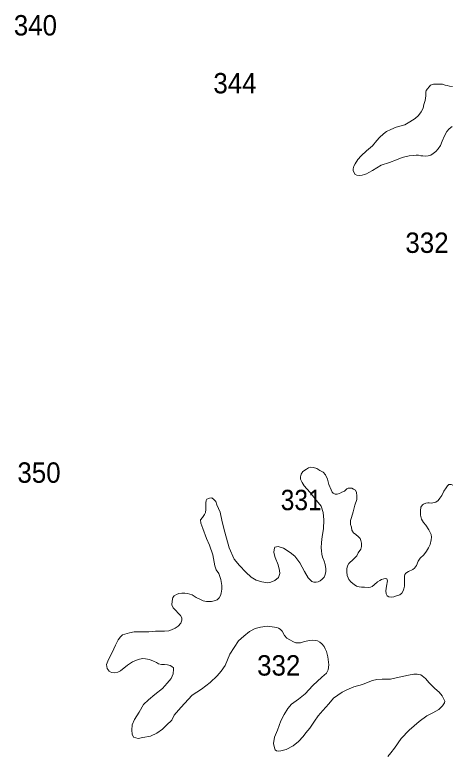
# Model space of a CAD drawing. Extents: x 445.4 to 500, y 8728.7 to 8784.
# Drawn here: x 464.51 to 467.93, y 8746.56 to 8752.36 of the extents above; entities that cross this region are included whole.
import ezdxf
from ezdxf.enums import TextEntityAlignment as Align

# ---------------------------------------------------------------- set-up
doc = ezdxf.new("R2010")
doc.units = 0
doc.header["$LTSCALE"] = 0.064
doc.layers.add('2', color=7, linetype='Continuous', lineweight=13)
doc.layers.add('21', color=7, linetype='Continuous')

msp = doc.modelspace()

# ---------------------------------------------------------------- linework, layer by layer
at = {"layer": '2'}
for points in [[(467.9412, 8751.4875), (467.9172, 8751.4684), (467.8981, 8751.4493), (467.8813, 8751.4134), (467.8633, 8751.374), (467.8502, 8751.3381), (467.8322, 8751.3118), (467.8118, 8751.2915), (467.7927, 8751.2748), (467.7747, 8751.2629), (467.752, 8751.2569), (467.7345, 8751.2553), (467.7117, 8751.2577), (467.695, 8751.2589), (467.6758, 8751.2625), (467.6578, 8751.2625), (467.6363, 8751.2613), (467.604, 8751.2565), (467.5489, 8751.2457), (467.5034, 8751.2266), (467.4495, 8751.2063), (467.3837, 8751.1848), (467.3162, 8751.1415), (467.2863, 8751.126), (467.2683, 8751.1164), (467.254, 8751.1105), (467.2336, 8751.1069), (467.2132, 8751.1045), (467.1929, 8751.1057), (467.1809, 8751.1105), (467.169, 8751.1284), (467.163, 8751.1427), (467.1642, 8751.1559), (467.169, 8751.1762), (467.1797, 8751.1941), (467.2013, 8751.2288), (467.2264, 8751.2574), (467.2695, 8751.2981), (467.315, 8751.3363), (467.3509, 8751.3769), (467.3715, 8751.4017), (467.4014, 8751.4292), (467.4253, 8751.4483), (467.4589, 8751.4638), (467.502, 8751.4817), (467.5702, 8751.5021), (467.6099, 8751.5248), (467.652, 8751.5502), (467.6757, 8751.5747), (467.6976, 8751.6027), (467.7125, 8751.6325), (467.7195, 8751.6596), (467.73, 8751.6929), (467.7336, 8751.7297), (467.7336, 8751.7574), (467.738, 8751.7705), (467.7468, 8751.7845), (467.7599, 8751.7985), (467.7722, 8751.8108), (467.788, 8751.8169), (467.7959, 8751.8195), (467.8161, 8751.8195), (467.8459, 8751.8204), (467.8652, 8751.8187), (467.8871, 8751.8125), (467.902, 8751.809), (467.9196, 8751.8047), (467.9441, 8751.8012)], [(466.3231, 8747.9933), (466.3636, 8747.9528), (466.4037, 8747.929), (466.4464, 8747.9165), (466.4916, 8747.909), (466.5192, 8747.914), (466.5493, 8747.9265), (466.5795, 8747.9516), (466.5895, 8747.9817), (466.587, 8748.0042), (466.5745, 8748.0493), (466.5519, 8748.107), (466.5418, 8748.1471), (466.5443, 8748.1696), (466.5493, 8748.1871), (466.5745, 8748.1947), (466.6171, 8748.1796), (466.6699, 8748.1471), (466.7075, 8748.117), (466.7452, 8748.0644), (466.7829, 8747.9967), (466.8105, 8747.9466), (466.8409, 8747.9188), (466.8558, 8747.9141), (466.8735, 8747.9141), (466.8903, 8747.916), (466.9061, 8747.9253), (466.9219, 8747.9383), (466.9377, 8747.9531), (466.9414, 8747.9652), (466.9498, 8747.9949), (466.9498, 8748.0191), (466.9452, 8748.0525), (466.9358, 8748.0785), (466.9228, 8748.111), (466.9182, 8748.1342), (466.9146, 8748.159), (466.9128, 8748.1841), (466.9156, 8748.2259), (466.9211, 8748.2733), (466.9304, 8748.3309), (466.9336, 8748.4035), (466.9285, 8748.4591), (466.9133, 8748.5097), (466.8753, 8748.5552), (466.8247, 8748.6209), (466.7791, 8748.6689), (466.763, 8748.6946), (466.7519, 8748.7228), (466.7519, 8748.7413), (466.7569, 8748.7597), (466.7692, 8748.7818), (466.7975, 8748.8014), (466.8135, 8748.8112), (466.8331, 8748.8149), (466.8528, 8748.8137), (466.8787, 8748.8051), (466.9033, 8748.7891), (466.9279, 8748.7756), (466.9463, 8748.7548), (466.9623, 8748.7228), (466.9734, 8748.6811), (466.9906, 8748.6369), (466.9992, 8748.6197), (467.0078, 8748.6111), (467.0226, 8748.605), (467.0386, 8748.605), (467.057, 8748.6087), (467.0755, 8748.6185), (467.0964, 8748.6271), (467.1139, 8748.6462), (467.1259, 8748.6499), (467.1408, 8748.6518), (467.1528, 8748.6499), (467.1658, 8748.6443), (467.1816, 8748.636), (467.1909, 8748.6184), (467.1937, 8748.5897), (467.1918, 8748.5619), (467.177, 8748.5174), (467.1649, 8748.4665), (467.1502, 8748.4212), (467.1446, 8748.3971), (467.1437, 8748.3674), (467.1511, 8748.3443), (467.1548, 8748.322), (467.1678, 8748.3007), (467.1855, 8748.2878), (467.2059, 8748.2702), (467.2195, 8748.2559), (467.2254, 8748.2395), (467.2299, 8748.2186), (467.2284, 8748.1948), (467.2239, 8748.1724), (467.203, 8748.1427), (467.1926, 8748.1203), (467.1657, 8748.095), (467.1314, 8748.0607), (467.121, 8748.0429), (467.115, 8748.019), (467.1135, 8747.9952)], [(467.1135, 8747.9952), (467.1165, 8747.9669), (467.1254, 8747.9475), (467.1314, 8747.9356), (467.1479, 8747.9141), (467.1733, 8747.8948), (467.1912, 8747.8814), (467.2106, 8747.8769), (467.23, 8747.8739), (467.2539, 8747.8754), (467.2808, 8747.8724), (467.3002, 8747.8754), (467.3121, 8747.8799), (467.33, 8747.8918), (467.3554, 8747.9156), (467.3748, 8747.9275), (467.3867, 8747.935), (467.4047, 8747.9409), (467.4196, 8747.9424), (467.4285, 8747.9409), (467.433, 8747.9246), (467.4256, 8747.8814), (467.4211, 8747.8456), (467.4226, 8747.8233), (467.43, 8747.8069), (467.4435, 8747.7979), (467.4629, 8747.795), (467.4838, 8747.7979), (467.5032, 8747.8054), (467.53, 8747.8143), (467.545, 8747.8277), (467.5554, 8747.8456), (467.5629, 8747.862), (467.5673, 8747.8814), (467.5658, 8747.9126), (467.5658, 8747.9409), (467.5658, 8747.9603), (467.5703, 8747.9737), (467.5778, 8747.9841), (467.5987, 8747.9975), (467.6315, 8748.0139), (467.645, 8748.0229), (467.6614, 8748.0437), (467.6748, 8748.0795), (467.6897, 8748.1018), (467.7181, 8748.1286), (467.7395, 8748.1564), (467.7559, 8748.1832), (467.7694, 8748.2085), (467.7768, 8748.2458), (467.7783, 8748.2666), (467.7753, 8748.2875), (467.7589, 8748.3233), (467.735, 8748.362), (467.7156, 8748.3813), (467.7007, 8748.4082), (467.6918, 8748.4394), (467.6933, 8748.4745), (467.6963, 8748.5014), (467.7082, 8748.5207), (467.7157, 8748.5267), (467.7336, 8748.5326), (467.75, 8748.5356), (467.7604, 8748.5356), (467.7798, 8748.5341), (467.8142, 8748.5416), (467.8306, 8748.555), (467.8455, 8748.5714), (467.8604, 8748.5937), (467.8754, 8748.6265), (467.8933, 8748.6548), (467.9037, 8748.6682), (467.9157, 8748.6786), (467.9321, 8748.6801), (467.947, 8748.6742)], [(465.7509, 8747.1954), (465.753, 8747.2315), (465.753, 8747.2422), (465.7424, 8747.2528), (465.7274, 8747.2613), (465.7061, 8747.2656), (465.6848, 8747.2677), (465.6592, 8747.2677), (465.6358, 8747.2741), (465.6209, 8747.2847), (465.5974, 8747.2954), (465.5655, 8747.3081), (465.5356, 8747.3124), (465.5122, 8747.3145), (465.4781, 8747.3081), (465.4312, 8747.289), (465.3928, 8747.2634), (465.3374, 8747.2188), (465.3182, 8747.2081), (465.2884, 8747.2039), (465.2671, 8747.206), (465.2501, 8747.2145), (465.233, 8747.2379), (465.2287, 8747.2677), (465.2437, 8747.306), (465.2735, 8747.3634), (465.2991, 8747.4209), (465.3204, 8747.4613), (465.3396, 8747.4847), (465.3545, 8747.4996), (465.4078, 8747.5166), (465.4461, 8747.523), (465.4951, 8747.5251), (465.5612, 8747.5251), (465.6124, 8747.5293), (465.6529, 8747.5293), (465.6827, 8747.5293), (465.7168, 8747.5315), (465.7381, 8747.54), (465.7679, 8747.5527), (465.7914, 8747.5676), (465.8106, 8747.5932), (465.8194, 8747.6158), (465.8194, 8747.6328), (465.8088, 8747.6519), (465.7938, 8747.6689), (465.7704, 8747.6945), (465.7512, 8747.7115), (465.7406, 8747.7349), (465.7427, 8747.7647), (465.7491, 8747.7944), (465.7597, 8747.8072), (465.7768, 8747.8178), (465.796, 8747.8242), (465.8194, 8747.8285), (465.8429, 8747.8285), (465.8642, 8747.8242), (465.9004, 8747.8136), (465.9324, 8747.7923), (465.9707, 8747.7753), (465.9878, 8747.7668), (466.0134, 8747.7625), (466.0347, 8747.7625), (466.0517, 8747.7625), (466.073, 8747.7668), (466.0965, 8747.7753), (466.1135, 8747.7902), (466.1242, 8747.8093), (466.1284, 8747.8285), (466.1348, 8747.8583), (466.1348, 8747.888), (466.1263, 8747.9348), (466.1093, 8747.9816), (466.0903, 8748.0105), (466.0797, 8748.0424), (466.0626, 8748.1275), (466.0371, 8748.2041), (466.0136, 8748.2551), (465.9838, 8748.336), (465.969, 8748.3775), (465.9669, 8748.403), (465.9818, 8748.42), (465.9967, 8748.4434), (466.0052, 8748.4605), (466.0074, 8748.4839), (466.0074, 8748.5115), (466.0074, 8748.537), (466.0116, 8748.5541), (466.0159, 8748.5647), (466.0372, 8748.5732), (466.0542, 8748.5753), (466.0713, 8748.5626), (466.0862, 8748.5477), (466.0947, 8748.52), (466.1203, 8748.4626), (466.1374, 8748.3881), (466.1565, 8748.3073), (466.1906, 8748.1839), (466.2315, 8748.0932), (466.272, 8748.0443), (466.3231, 8747.9933)], [(467.6402, 8747.1921), (467.5986, 8747.1846), (467.5243, 8747.1698), (467.456, 8747.1535), (467.3906, 8747.1535), (467.349, 8747.1505), (467.3163, 8747.1416), (467.2821, 8747.1298), (467.2376, 8747.112), (467.1692, 8747.0927), (467.1143, 8747.069), (467.0779, 8747.0507), (467.0437, 8747.0285), (467.0111, 8747.0033), (466.9724, 8746.9588), (466.9264, 8746.9069), (466.8907, 8746.8654), (466.861, 8746.8239), (466.8249, 8746.7698), (466.7937, 8746.7313), (466.7715, 8746.7031), (466.7343, 8746.663), (466.6927, 8746.6304), (466.6378, 8746.6008), (466.5962, 8746.5904), (466.5768, 8746.5889), (466.562, 8746.5919), (466.5516, 8746.5993), (466.5456, 8746.6156), (466.5397, 8746.6497), (466.5471, 8746.6986), (466.5694, 8746.7535), (466.5976, 8746.8262), (466.6229, 8746.8766), (466.6511, 8746.9225), (466.6793, 8746.9566), (466.7347, 8746.9973), (466.7883, 8747.0373), (466.8485, 8747.1025), (466.9188, 8747.1676), (466.9557, 8747.201), (466.969, 8747.2261), (466.9741, 8747.2662), (466.9657, 8747.328), (466.954, 8747.3688), (466.9439, 8747.3905), (466.9355, 8747.4105), (466.9188, 8747.4289), (466.9038, 8747.4423), (466.8853, 8747.454), (466.8703, 8747.4556), (466.8468, 8747.459), (466.8217, 8747.4573), (466.7816, 8747.4473), (466.7498, 8747.4389), (466.7297, 8747.4372), (466.713, 8747.4389), (466.6962, 8747.4456), (466.6661, 8747.4606), (466.6443, 8747.4757), (466.6243, 8747.4957), (466.6075, 8747.5308), (466.5925, 8747.5442), (466.5791, 8747.5542), (466.564, 8747.5592), (466.5473, 8747.5609), (466.4881, 8747.5676), (466.4379, 8747.5609), (466.396, 8747.5492), (466.3508, 8747.5258), (466.3057, 8747.4891), (466.2655, 8747.454), (466.1952, 8747.3488), (466.1584, 8747.2603), (466.1283, 8747.2152), (466.0961, 8747.1793), (466.0408, 8747.1275), (465.9739, 8747.0758), (465.9019, 8747.0273), (465.813, 8746.9313), (465.7594, 8746.8712), (465.741, 8746.8311), (465.7002, 8746.7911), (465.6667, 8746.7602), (465.6229, 8746.7294), (465.5739, 8746.7062), (465.5146, 8746.6959), (465.476, 8746.6882), (465.4399, 8746.6985), (465.4296, 8746.7216), (465.427, 8746.7525), (465.4296, 8746.7937), (465.4476, 8746.8374), (465.4837, 8746.894), (465.5198, 8746.9532), (465.5584, 8746.9917), (465.6074, 8747.0329), (465.6667, 8747.0792), (465.7053, 8747.1204), (465.736, 8747.1571), (465.7509, 8747.1954)], [(467.4363, 8746.5461), (467.4586, 8746.5742), (467.4883, 8746.6128), (467.542, 8746.688), (467.6029, 8746.7518), (467.6817, 8746.8215), (467.7426, 8746.866), (467.7886, 8746.8882), (467.8362, 8746.9149), (467.8659, 8746.9431), (467.8811, 8746.9662), (467.8826, 8746.9811), (467.8767, 8746.9974), (467.8618, 8747.0226), (467.838, 8747.0507), (467.8053, 8747.0804), (467.7608, 8747.1234), (467.7311, 8747.159), (467.707, 8747.1787), (467.6952, 8747.1876), (467.6788, 8747.1891), (467.6654, 8747.1921), (467.6402, 8747.1921)]]:
    msp.add_lwpolyline(points, dxfattribs=at)

# ---------------------------------------------------------------- texts
at = {"layer": '21', "width": 0.95}
msp.add_text('340', height=0.16, dxfattribs=at).set_placement((464.84, 8752.2017), align=Align.RIGHT)
at = {"layer": '21'}
for s, width, p in [('344', 0.95, (466.0671, 8751.7476)), ('332', 0.95, (467.5741, 8750.4964)), ('350', 0.95, (464.5291, 8748.6934)), ('331', 0.9, (466.5958, 8748.4784)), ('332', 0.95, (466.4106, 8747.181))]:
    msp.add_text(s, height=0.16, dxfattribs=dict(at, width=width)).set_placement(p)

doc.saveas('drawing.dxf')
